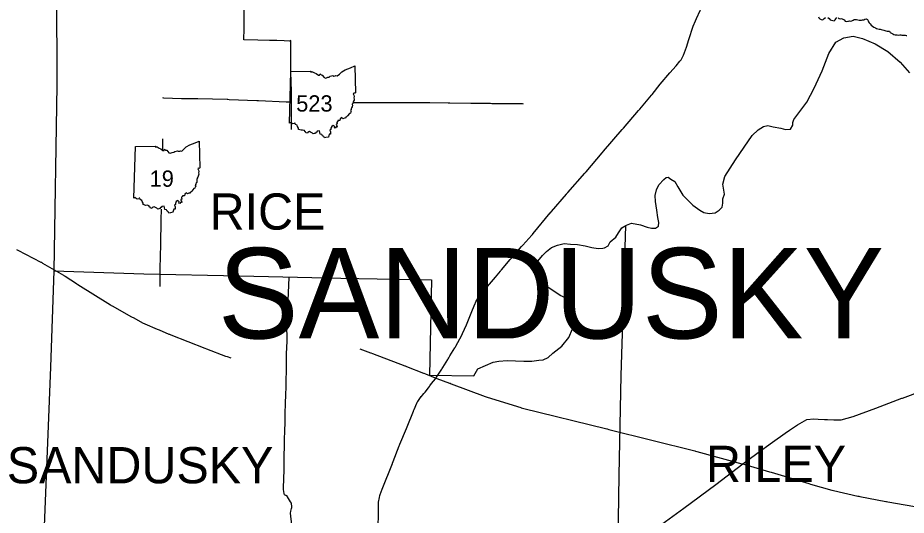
# Model space of a CAD drawing. Extents: x -232 to 448, y 619 to 1059.
# Drawn here: x 271.8 to 322.1, y 826.8 to 855 of the extents above; entities that cross this region are included whole.
import ezdxf

# ---------------------------------------------------------------- set-up
doc = ezdxf.new("R2010")
doc.units = 0
doc.layers.add('Default', color=7, linetype='Continuous')

msp = doc.modelspace()

# ---------------------------------------------------------------- linework, layer by layer
at = {"layer": 'Default'}
for p, q in [((287.166, 849.026), (287.248, 851.955)), ((287.166, 849.026), (287.248, 851.955)), ((278.363, 844.771), (278.445, 847.7)), ((278.363, 844.771), (278.445, 847.7))]:
    msp.add_line(p, q, dxfattribs=at)
for points in [[(273.981, 856.583), (273.991, 851.155), (273.816, 840.668)], [(287.247, 851.805), (287.244, 851.92), (287.247, 852.372), (287.245, 852.809), (287.243, 853.266), (287.244, 853.698), (287.166, 853.673), (286.866, 853.688), (286.447, 853.698), (286.03, 853.705), (285.384, 853.719), (284.579, 853.738), (284.606, 854.384), (284.609, 854.825), (284.609, 855.28), (284.608, 855.913), (284.602, 856.424)], [(310.153, 854.822), (310.209, 854.949), (310.427, 855.407), (310.633, 855.822), (310.793, 856.176)], [(309.276, 852.534), (309.345, 852.616), (309.472, 852.882), (309.645, 853.319), (309.786, 853.77), (310.02, 854.519), (310.153, 854.822)], [(317.128, 855.046), (317.148, 854.99), (317.207, 854.922), (317.272, 854.886), (317.326, 854.877), (317.392, 854.897), (317.442, 854.958), (317.511, 855.004)], [(317.655, 855.013), (317.722, 854.95), (317.791, 854.877), (317.861, 854.852), (317.928, 854.828), (318.005, 854.827), (318.073, 854.872), (318.109, 854.937), (318.165, 855.009)], [(318.233, 854.991), (318.298, 854.945), (318.364, 854.924), (318.434, 854.942), (318.506, 854.918), (318.575, 854.874), (318.634, 854.801), (318.706, 854.78), (318.776, 854.791), (318.83, 854.805), (318.883, 854.81), (318.955, 854.807), (319.009, 854.817), (319.082, 854.857), (319.15, 854.894), (319.202, 854.901), (319.272, 854.898), (319.349, 854.875), (319.423, 854.851), (319.489, 854.846), (319.559, 854.86), (319.619, 854.876), (319.689, 854.883), (319.753, 854.903), (319.819, 854.923), (319.893, 854.899), (319.942, 854.826), (319.962, 854.76), (319.994, 854.706), (320.053, 854.641), (320.114, 854.571), (320.185, 854.514), (320.261, 854.464), (320.343, 854.424), (320.416, 854.39)], [(320.416, 854.39), (320.482, 854.36), (320.558, 854.341), (320.609, 854.34), (320.681, 854.318), (320.741, 854.305), (320.819, 854.286), (320.876, 854.262), (320.936, 854.245), (321.006, 854.238), (321.061, 854.237), (321.135, 854.226), (321.186, 854.166), (321.253, 854.12), (321.329, 854.082), (321.396, 854.042), (321.464, 854.018), (321.526, 854.028), (321.582, 854.025), (321.651, 854.006), (321.726, 854.021), (321.792, 854.027), (321.845, 854.011), (321.911, 854.004), (321.966, 854.008), (322.022, 854.007), (322.079, 853.99), (322.133, 853.987)], [(314.989, 848.734), (315.253, 848.674), (315.537, 848.694), (315.667, 848.904), (315.672, 849.068), (315.728, 849.24), (316.469, 850.209), (316.883, 851.001), (317.329, 851.988), (317.709, 852.972), (318.11, 853.605), (318.549, 853.86), (319.083, 853.951), (319.606, 853.813), (320.332, 853.509), (321.055, 853.075), (321.739, 852.472), (322.27, 851.873)], [(287.248, 851.955), (288.385, 851.974), (288.367, 851.939), (288.474, 851.931), (288.588, 851.869), (288.684, 851.829), (288.802, 851.736), (288.873, 851.737), (288.903, 851.813), (288.956, 851.754), (289.021, 851.744), (289.131, 851.604), (289.223, 851.573), (289.332, 851.621), (289.414, 851.629), (289.474, 851.677), (289.63, 851.717), (289.673, 851.693), (289.756, 851.698), (289.798, 851.716), (289.87, 851.7), (289.996, 851.806), (290.127, 851.932), (290.328, 852.05), (290.627, 852.163), (290.864, 852.263), (290.899, 850.743)], [(287.248, 851.955), (288.385, 851.974), (288.367, 851.939), (288.474, 851.931), (288.588, 851.869), (288.684, 851.829), (288.802, 851.736), (288.873, 851.737), (288.903, 851.813), (288.956, 851.754), (289.021, 851.744), (289.131, 851.604), (289.223, 851.573), (289.332, 851.621), (289.414, 851.629), (289.474, 851.677), (289.63, 851.717), (289.673, 851.693), (289.756, 851.698), (289.798, 851.716), (289.87, 851.7), (289.996, 851.806), (290.127, 851.932), (290.328, 852.05), (290.627, 852.163), (290.864, 852.263), (290.899, 850.743)], [(298.832, 840.315), (299.113, 840.644), (299.139, 840.675), (299.183, 840.727), (299.672, 841.308), (299.699, 841.34), (299.743, 841.39), (300.314, 842.045), (300.337, 842.071), (300.386, 842.126), (300.894, 842.69), (300.921, 842.72), (300.965, 842.773), (301.933, 843.944), (301.939, 843.952), (302.003, 844.026), (302.854, 845.013), (302.857, 845.017), (302.925, 845.094), (303.891, 846.196), (303.902, 846.209), (303.962, 846.278), (304.881, 847.349), (304.886, 847.355), (304.952, 847.431), (306.014, 848.665), (306.028, 848.681), (306.084, 848.747), (306.929, 849.738), (306.946, 849.758), (307, 849.821), (307.673, 850.602), (307.709, 850.644), (308.162, 851.238), (308.705, 851.871), (309.055, 852.273), (309.276, 852.534)], [(287.27, 851.204), (287.254, 851.487), (287.247, 851.805)], [(287.273, 850.229), (287.273, 850.284), (287.273, 850.306), (287.274, 850.392), (287.282, 850.933), (287.283, 850.987), (287.27, 851.204)], [(290.899, 850.743), (290.864, 850.722), (290.809, 850.732), (290.773, 850.689), (290.818, 850.618), (290.839, 850.543), (290.82, 850.46), (290.839, 850.392), (290.826, 850.335), (290.792, 850.278), (290.78, 850.224), (290.751, 850.166), (290.754, 850.134), (290.726, 850.109), (290.731, 850.014), (290.717, 849.961), (290.722, 849.916), (290.677, 849.904), (290.687, 849.866), (290.658, 849.837), (290.664, 849.787), (290.632, 849.756), (290.664, 849.692), (290.638, 849.672), (290.617, 849.594), (290.559, 849.578), (290.444, 849.437), (290.403, 849.383), (290.357, 849.37), (290.332, 849.314), (290.276, 849.314), (290.19, 849.276), (290.135, 849.342), (290.038, 849.263), (290.027, 849.171), (289.905, 849.174), (289.91, 849.128), (289.883, 849.115), (289.858, 849.068), (289.872, 848.986), (289.815, 848.965), (289.822, 848.918), (289.858, 848.888), (289.875, 848.797), (289.814, 848.816), (289.764, 848.739), (289.713, 848.757), (289.73, 848.822), (289.643, 848.9), (289.561, 848.838), (289.518, 848.737), (289.518, 848.67), (289.457, 848.629), (289.496, 848.534), (289.489, 848.468), (289.49, 848.406), (289.414, 848.408), (289.368, 848.24)], [(290.899, 850.743), (290.864, 850.722), (290.809, 850.732), (290.773, 850.689), (290.818, 850.618), (290.839, 850.543), (290.82, 850.46), (290.839, 850.392), (290.826, 850.335), (290.792, 850.278), (290.78, 850.224), (290.751, 850.166), (290.754, 850.134), (290.726, 850.109), (290.731, 850.014), (290.717, 849.961), (290.722, 849.916), (290.677, 849.904), (290.687, 849.866), (290.658, 849.837), (290.664, 849.787), (290.632, 849.756), (290.664, 849.692), (290.638, 849.672), (290.617, 849.594), (290.559, 849.578), (290.444, 849.437), (290.403, 849.383), (290.357, 849.37), (290.332, 849.314), (290.276, 849.314), (290.19, 849.276), (290.135, 849.342), (290.038, 849.263), (290.027, 849.171), (289.905, 849.174), (289.91, 849.128), (289.883, 849.115), (289.858, 849.068), (289.872, 848.986), (289.815, 848.965), (289.822, 848.918), (289.858, 848.888), (289.875, 848.797), (289.814, 848.816), (289.764, 848.739), (289.713, 848.757), (289.73, 848.822), (289.643, 848.9), (289.561, 848.838), (289.518, 848.737), (289.518, 848.67), (289.457, 848.629), (289.496, 848.534), (289.489, 848.468), (289.49, 848.406), (289.414, 848.408), (289.368, 848.24)], [(279.982, 850.47), (280.036, 850.467), (281.059, 850.416), (281.091, 850.415), (281.166, 850.416), (281.867, 850.427), (281.916, 850.428), (281.975, 850.427), (283.645, 850.378), (283.673, 850.377), (283.753, 850.373), (285.315, 850.305), (285.321, 850.305), (285.422, 850.301), (286.985, 850.24), (287.023, 850.239), (287.092, 850.237), (287.2, 850.235)], [(287.289, 848.661), (287.279, 849.364), (287.279, 849.402), (287.278, 849.472), (287.273, 850.229)], [(290.776, 850.203), (290.919, 850.202), (290.955, 850.202), (291.027, 850.201), (292.267, 850.196), (292.27, 850.195), (292.375, 850.195), (293.507, 850.188), (293.56, 850.187), (293.614, 850.187), (295.016, 850.194), (295.029, 850.193), (295.124, 850.192), (296.148, 850.171), (296.183, 850.171), (296.255, 850.17), (297.441, 850.15), (297.443, 850.15), (297.549, 850.15), (298.519, 850.148), (298.558, 850.148), (298.627, 850.147), (299.544, 850.142), (299.564, 850.142), (299.651, 850.14), (300.352, 850.129), (300.408, 850.128)], [(289.368, 848.24), (289.235, 848.208), (289.143, 848.189), (289.11, 848.265), (289.045, 848.305), (289.002, 848.382), (288.907, 848.393), (288.885, 848.498), (288.874, 848.584), (288.745, 848.563), (288.71, 848.51), (288.664, 848.496), (288.637, 848.444), (288.575, 848.439), (288.508, 848.414), (288.464, 848.466), (288.354, 848.518), (288.304, 848.545), (288.201, 848.503), (288.179, 848.454), (288.097, 848.476), (288.078, 848.531), (288.028, 848.547), (288.017, 848.605), (287.911, 848.637), (287.829, 848.624), (287.686, 848.671), (287.677, 848.748), (287.628, 848.841), (287.603, 848.906), (287.512, 848.956), (287.494, 849.033), (287.465, 849.031), (287.438, 849), (287.337, 848.985), (287.297, 849.017), (287.241, 849.071), (287.166, 849.026)], [(289.368, 848.24), (289.235, 848.208), (289.143, 848.189), (289.11, 848.265), (289.045, 848.305), (289.002, 848.382), (288.907, 848.393), (288.885, 848.498), (288.874, 848.584), (288.745, 848.563), (288.71, 848.51), (288.664, 848.496), (288.637, 848.444), (288.575, 848.439), (288.508, 848.414), (288.464, 848.466), (288.354, 848.518), (288.304, 848.545), (288.201, 848.503), (288.179, 848.454), (288.097, 848.476), (288.078, 848.531), (288.028, 848.547), (288.017, 848.605), (287.911, 848.637), (287.829, 848.624), (287.686, 848.671), (287.677, 848.748), (287.628, 848.841), (287.603, 848.906), (287.512, 848.956), (287.494, 849.033), (287.465, 849.031), (287.438, 849), (287.337, 848.985), (287.297, 849.017), (287.241, 849.071), (287.166, 849.026)], [(307.662, 843.083), (307.9, 843.085), (308.059, 843.196), (308.074, 843.401), (308.027, 843.686), (307.964, 844.098), (307.9, 844.588), (307.884, 844.921), (307.948, 845.253), (308.074, 845.538), (308.359, 845.838), (308.502, 845.949), (308.612, 845.965), (308.771, 845.854), (308.992, 845.728), (309.15, 845.411), (309.435, 844.952), (309.704, 844.683), (310.005, 844.383), (310.4, 844.098), (310.638, 843.971), (310.938, 843.908), (311.271, 843.955), (311.492, 844.098), (311.666, 844.272), (311.714, 844.493), (311.714, 844.746), (311.793, 845), (311.698, 845.569), (311.825, 846.012), (312.426, 846.946), (312.916, 847.658), (313.375, 848.323), (313.708, 848.639), (314.008, 848.845), (314.261, 848.892), (314.562, 848.813), (314.989, 848.734)], [(278.445, 847.7), (279.582, 847.719), (279.564, 847.683), (279.671, 847.676), (279.785, 847.613), (279.881, 847.574), (279.999, 847.481), (280.07, 847.482), (280.099, 847.558), (280.153, 847.499), (280.217, 847.489), (280.328, 847.348), (280.42, 847.318), (280.529, 847.366), (280.611, 847.374), (280.671, 847.422), (280.827, 847.462), (280.87, 847.438), (280.953, 847.443), (280.994, 847.461), (281.067, 847.445), (281.193, 847.551), (281.324, 847.677), (281.524, 847.795), (281.824, 847.907), (282.061, 848.008), (282.096, 846.488)], [(278.445, 847.7), (279.582, 847.719), (279.564, 847.683), (279.671, 847.676), (279.785, 847.613), (279.881, 847.574), (279.999, 847.481), (280.07, 847.482), (280.099, 847.558), (280.153, 847.499), (280.217, 847.489), (280.328, 847.348), (280.42, 847.318), (280.529, 847.366), (280.611, 847.374), (280.671, 847.422), (280.827, 847.462), (280.87, 847.438), (280.953, 847.443), (280.994, 847.461), (281.067, 847.445), (281.193, 847.551), (281.324, 847.677), (281.524, 847.795), (281.824, 847.907), (282.061, 848.008), (282.096, 846.488)], [(279.993, 847.486), (279.992, 847.82), (279.992, 847.847), (279.991, 847.928), (279.988, 848.144)], [(282.096, 846.488), (282.061, 846.467), (282.006, 846.477), (281.969, 846.434), (282.015, 846.363), (282.036, 846.288), (282.017, 846.205), (282.036, 846.137), (282.023, 846.079), (281.989, 846.022), (281.977, 845.968), (281.948, 845.911), (281.95, 845.879), (281.923, 845.854), (281.928, 845.759), (281.914, 845.706), (281.919, 845.661), (281.874, 845.649), (281.884, 845.611), (281.855, 845.582), (281.861, 845.532), (281.829, 845.5), (281.86, 845.437), (281.835, 845.416), (281.814, 845.339), (281.756, 845.323), (281.641, 845.181), (281.6, 845.128), (281.554, 845.114), (281.529, 845.059), (281.473, 845.059), (281.387, 845.021), (281.332, 845.087), (281.235, 845.007), (281.224, 844.916), (281.102, 844.919), (281.107, 844.873), (281.079, 844.859), (281.055, 844.813), (281.069, 844.731), (281.012, 844.71), (281.019, 844.662), (281.055, 844.633), (281.072, 844.542), (281.011, 844.56), (280.961, 844.484), (280.91, 844.502), (280.927, 844.567), (280.84, 844.645), (280.758, 844.582), (280.715, 844.482), (280.715, 844.415), (280.654, 844.374), (280.693, 844.279), (280.686, 844.213), (280.687, 844.151), (280.611, 844.153), (280.565, 843.985)], [(282.096, 846.488), (282.061, 846.467), (282.006, 846.477), (281.969, 846.434), (282.015, 846.363), (282.036, 846.288), (282.017, 846.205), (282.036, 846.137), (282.023, 846.079), (281.989, 846.022), (281.977, 845.968), (281.948, 845.911), (281.95, 845.879), (281.923, 845.854), (281.928, 845.759), (281.914, 845.706), (281.919, 845.661), (281.874, 845.649), (281.884, 845.611), (281.855, 845.582), (281.861, 845.532), (281.829, 845.5), (281.86, 845.437), (281.835, 845.416), (281.814, 845.339), (281.756, 845.323), (281.641, 845.181), (281.6, 845.128), (281.554, 845.114), (281.529, 845.059), (281.473, 845.059), (281.387, 845.021), (281.332, 845.087), (281.235, 845.007), (281.224, 844.916), (281.102, 844.919), (281.107, 844.873), (281.079, 844.859), (281.055, 844.813), (281.069, 844.731), (281.012, 844.71), (281.019, 844.662), (281.055, 844.633), (281.072, 844.542), (281.011, 844.56), (280.961, 844.484), (280.91, 844.502), (280.927, 844.567), (280.84, 844.645), (280.758, 844.582), (280.715, 844.482), (280.715, 844.415), (280.654, 844.374), (280.693, 844.279), (280.686, 844.213), (280.687, 844.151), (280.611, 844.153), (280.565, 843.985)], [(280.565, 843.985), (280.432, 843.953), (280.34, 843.933), (280.307, 844.01), (280.242, 844.05), (280.199, 844.127), (280.104, 844.137), (280.082, 844.243), (280.071, 844.329), (279.942, 844.308), (279.906, 844.255), (279.861, 844.241), (279.834, 844.188), (279.772, 844.184), (279.705, 844.159), (279.661, 844.211), (279.551, 844.263), (279.501, 844.29), (279.398, 844.248), (279.376, 844.199), (279.294, 844.22), (279.275, 844.275), (279.225, 844.292), (279.214, 844.35), (279.108, 844.381), (279.026, 844.369), (278.883, 844.416), (278.874, 844.493), (278.825, 844.586), (278.8, 844.651), (278.709, 844.701), (278.691, 844.778), (278.662, 844.776), (278.635, 844.744), (278.534, 844.73), (278.494, 844.761), (278.438, 844.815), (278.363, 844.771)], [(280.565, 843.985), (280.432, 843.953), (280.34, 843.933), (280.307, 844.01), (280.242, 844.05), (280.199, 844.127), (280.104, 844.137), (280.082, 844.243), (280.071, 844.329), (279.942, 844.308), (279.906, 844.255), (279.861, 844.241), (279.834, 844.188), (279.772, 844.184), (279.705, 844.159), (279.661, 844.211), (279.551, 844.263), (279.501, 844.29), (279.398, 844.248), (279.376, 844.199), (279.294, 844.22), (279.275, 844.275), (279.225, 844.292), (279.214, 844.35), (279.108, 844.381), (279.026, 844.369), (278.883, 844.416), (278.874, 844.493), (278.825, 844.586), (278.8, 844.651), (278.709, 844.701), (278.691, 844.778), (278.662, 844.776), (278.635, 844.744), (278.534, 844.73), (278.494, 844.761), (278.438, 844.815), (278.363, 844.771)], [(279.843, 839.772), (279.845, 839.826), (279.846, 839.865), (279.847, 839.934), (279.852, 840.691), (279.852, 840.731), (279.854, 840.799), (279.889, 842.151), (279.889, 842.173), (279.89, 842.259), (279.905, 843.448), (279.906, 843.475), (279.908, 843.556), (279.927, 844.157)], [(297.609, 834.724), (297.836, 835.11), (298.707, 835.49), (299.023, 835.553), (299.498, 835.585), (299.973, 835.569), (300.432, 835.553), (300.89, 835.553), (301.286, 835.6), (301.539, 835.632), (301.808, 835.759), (302.077, 835.996), (302.584, 836.407), (302.979, 836.898), (303.201, 837.373), (303.296, 837.768), (303.311, 838.18), (303.296, 838.48), (303.201, 838.797), (303.042, 838.971), (302.805, 839.145), (302.504, 839.271), (301.508, 839.936), (301.239, 840.158), (301.144, 840.332), (301.08, 840.506), (301.096, 840.664), (301.159, 840.87), (301.239, 841.218), (301.492, 841.534), (301.729, 841.756), (302.014, 841.993), (302.346, 842.12), (302.726, 842.215), (303.074, 842.183), (303.485, 842.151), (303.913, 842.072), (304.292, 841.993), (304.656, 841.93), (304.91, 841.946), (305.005, 841.961), (305.21, 842.088), (305.321, 842.31), (305.653, 842.579), (305.796, 842.816), (305.986, 843.101), (306.215, 843.236)], [(305.585, 812.88), (305.828, 829.097), (305.95, 834.733), (306.115, 840.125), (306.215, 843.236)], [(306.215, 843.236), (306.255, 843.259), (306.539, 843.37), (307.046, 843.275), (307.426, 843.132), (307.662, 843.083)], [(271.709, 841.87), (271.79, 841.829), (273.097, 841.16), (273.118, 841.149), (273.192, 841.106), (274.368, 840.424), (274.393, 840.409), (274.46, 840.366), (275.099, 839.953), (275.127, 839.935), (275.191, 839.895), (277.028, 838.731), (277.065, 838.708), (277.122, 838.675), (278.214, 838.066), (278.256, 838.042), (278.309, 838.014), (278.886, 837.708), (278.932, 837.684), (278.984, 837.661), (279.685, 837.363), (279.737, 837.34), (279.787, 837.319), (280.34, 837.087), (280.379, 837.071), (280.441, 837.047), (282.368, 836.292), (282.371, 836.29), (282.469, 836.252), (283.537, 835.843), (283.57, 835.831), (283.64, 835.806), (283.844, 835.732)], [(273.816, 840.668), (273.632, 835.21), (272.76, 813.394)], [(273.816, 840.668), (278.912, 840.486), (284.336, 840.384), (290.082, 840.252)], [(286.998, 835.516), (287, 835.85), (287, 835.898), (287.003, 835.962), (287.03, 836.685), (287.031, 836.706), (287.03, 836.797), (287.026, 837.576), (287.026, 837.586), (287.031, 837.688), (287.039, 837.857), (287.041, 837.911), (287.086, 838.883), (287.088, 838.936), (287.09, 838.991), (287.144, 840.288)], [(290.082, 840.252), (295.201, 840.147), (295.096, 834.751)], [(296.251, 835.847), (296.528, 836.3), (296.544, 836.326), (296.582, 836.395), (296.919, 837.014), (296.921, 837.018), (296.963, 837.113), (297.185, 837.609), (297.188, 837.614), (297.226, 837.709), (297.492, 838.363), (297.493, 838.365), (297.532, 838.463), (297.676, 838.815), (297.695, 838.862), (297.724, 838.912), (297.886, 839.194), (297.892, 839.204), (297.954, 839.278), (298.302, 839.695), (298.312, 839.706), (298.373, 839.778), (298.832, 840.315)], [(321.847, 833.451), (321.887, 833.465), (322.492, 833.685), (322.855, 833.849), (323.382, 834.155), (323.782, 834.421), (324.253, 834.687), (325.222, 835.232), (326.04, 835.585), (327.431, 836.187), (328.849, 836.828), (329.053, 836.914)], [(291.146, 836.248), (291.761, 836.026), (291.777, 836.02), (291.862, 835.988), (293.697, 835.295)], [(295.499, 834.64), (295.788, 835.099), (295.812, 835.138), (295.845, 835.191), (296.132, 835.652), (296.147, 835.676), (296.189, 835.745), (296.251, 835.847)], [(286.858, 829.391), (286.864, 829.614), (286.864, 829.635), (286.866, 829.725), (286.875, 830.393), (286.875, 830.422), (286.877, 830.505), (286.892, 831.284), (286.893, 831.329), (286.896, 831.396), (286.928, 832.286), (286.928, 832.289), (286.931, 832.398), (286.95, 833.344), (286.951, 833.367), (286.953, 833.456), (286.976, 834.291), (286.977, 834.332), (286.979, 834.402), (286.995, 835.071), (286.996, 835.108), (286.997, 835.182), (286.998, 835.516)], [(293.697, 835.295), (293.728, 835.283), (293.798, 835.256), (294.762, 834.879), (294.774, 834.874), (294.863, 834.838), (295.419, 834.615), (295.47, 834.594)], [(295.096, 834.751), (297.609, 834.724)], [(295.434, 834.551), (295.47, 834.594), (295.499, 834.64)], [(294.779, 833.718), (294.852, 833.803), (294.852, 833.803), (294.921, 833.89), (295.025, 834.021), (295.047, 834.048), (295.089, 834.112), (295.12, 834.159)], [(295.12, 834.159), (295.151, 834.205), (295.174, 834.239), (295.219, 834.294), (295.434, 834.551)], [(295.47, 834.594), (295.521, 834.575), (296.23, 834.312), (296.269, 834.297), (296.331, 834.273), (298.252, 833.546), (298.252, 833.545), (298.355, 833.514), (300.266, 832.926), (300.296, 832.916), (300.37, 832.898), (305.144, 831.715), (305.154, 831.711), (305.248, 831.688), (310.123, 830.467), (310.164, 830.456), (310.227, 830.439), (312.783, 829.746), (312.838, 829.731), (312.89, 829.715), (314.343, 829.289), (314.368, 829.282), (314.447, 829.258), (316.571, 828.619), (316.579, 828.617), (316.675, 828.59), (317.873, 828.254), (317.902, 828.246), (317.978, 828.229), (319.35, 827.914), (319.402, 827.902), (319.455, 827.892), (320.943, 827.605), (320.967, 827.6), (321.049, 827.586), (323.022, 827.245)], [(292.19, 826.112), (292.201, 826.949), (292.202, 826.996), (292.202, 827.061), (292.205, 827.451), (292.206, 827.498), (292.215, 827.562), (292.258, 827.838), (292.258, 827.84), (292.293, 827.944), (292.382, 828.209), (292.393, 828.241), (292.421, 828.313), (293.001, 829.765), (293.008, 829.785), (293.041, 829.869), (293.38, 830.756), (293.392, 830.788), (293.421, 830.859), (293.787, 831.735), (293.789, 831.74), (293.829, 831.838), (294.188, 832.717), (294.198, 832.742), (294.231, 832.82), (294.384, 833.18), (294.401, 833.222), (294.439, 833.275), (294.633, 833.549), (294.638, 833.555), (294.706, 833.634), (294.779, 833.718)], [(318.314, 832.235), (318.399, 832.237), (319.091, 832.415), (320.369, 832.894), (321.847, 833.451)], [(315.488, 831.641), (315.93, 831.945), (316.459, 832.249), (316.859, 832.283), (317.102, 832.27)], [(317.102, 832.27), (317.471, 832.25)], [(317.471, 832.25), (317.635, 832.241), (317.991, 832.226), (318.314, 832.235)], [(302.47, 822.022), (302.908, 822.358), (303.825, 823.018), (303.918, 823.1), (305.522, 824.311), (305.73, 824.465), (306.691, 825.164), (308.087, 826.196), (308.469, 826.48), (309.506, 827.224), (311.312, 828.576), (312.838, 829.731), (313.639, 830.323), (314.523, 830.957), (315.245, 831.474), (315.488, 831.641)], [(287.279, 826.169), (287.273, 826.503), (287.272, 826.558), (287.265, 826.614), (287.227, 826.946), (287.226, 826.955), (287.25, 827.055), (287.289, 827.217), (287.3, 827.265), (287.294, 827.327), (287.277, 827.493), (287.274, 827.52), (287.231, 827.593), (287.061, 827.88), (287.058, 827.885), (286.967, 827.939), (286.919, 827.967), (286.885, 827.987), (286.872, 828.058), (286.831, 828.277), (286.829, 828.29), (286.831, 828.388), (286.858, 829.391)]]:
    msp.add_lwpolyline(points, dxfattribs=at)

# ---------------------------------------------------------------- texts
for s, height, p in [('523', 0.9234, (287.547, 849.679)), ('19', 0.9234, (279.249, 845.424)), ('RICE', 2.052, (282.644, 842.996)), ('SANDUSKY', 5.13, (283.109, 836.835)), ('SANDUSKY', 2.052, (271.161, 828.636)), ('RILEY', 2.052, (310.753, 828.71))]:
    msp.add_text(s, height=height, dxfattribs=at).set_placement(p)

doc.saveas('drawing.dxf')
